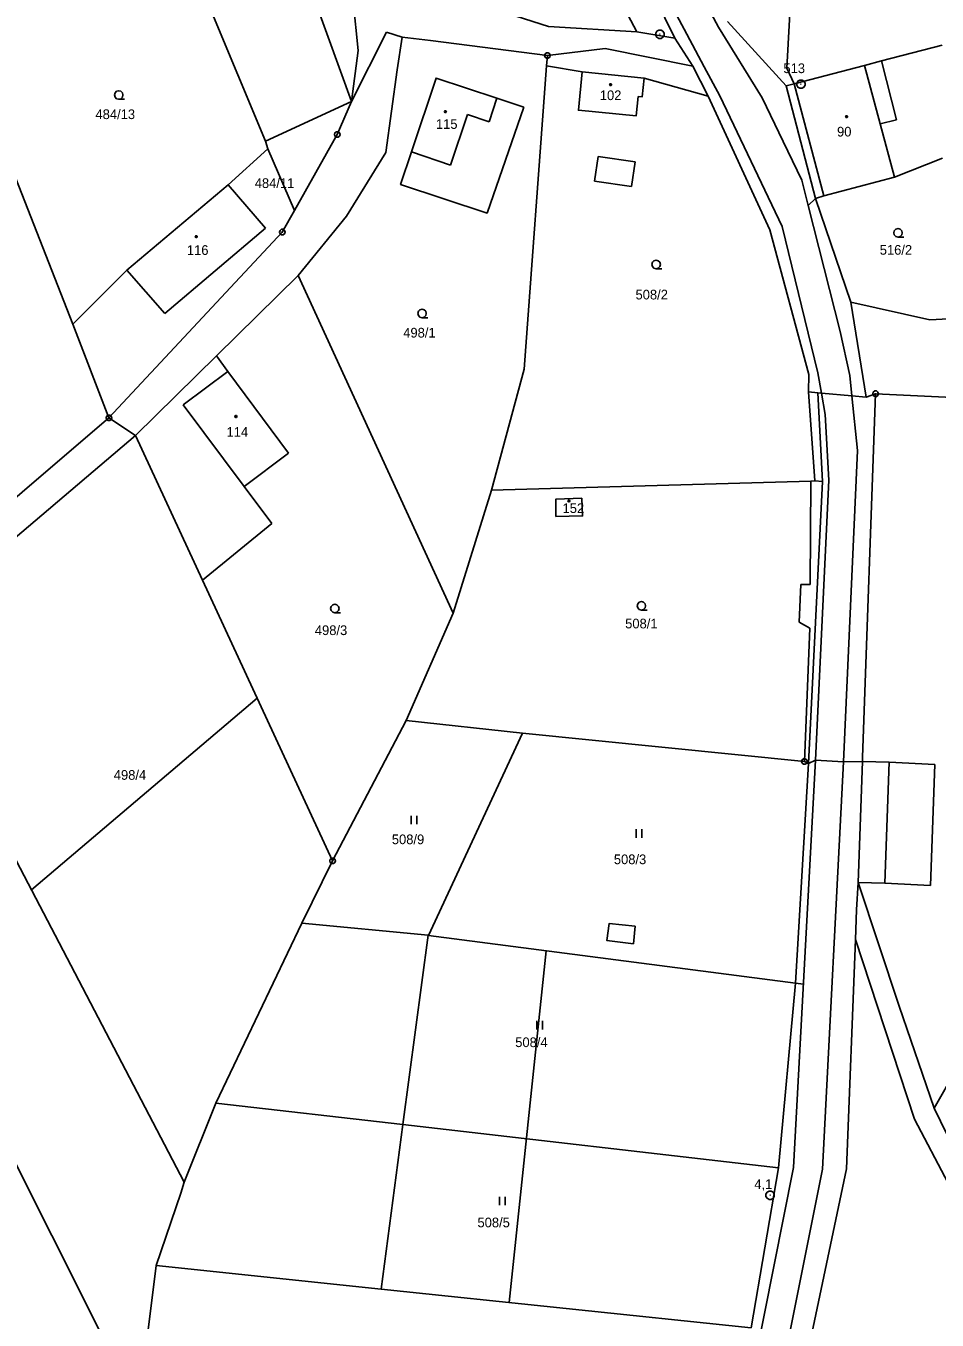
# Model space of a CAD drawing. Extents: x -694465 to -690527, y -983694 to -978978.
# Drawn here: x -693633.5 to -693473.5, y -981788.7 to -981561.4 of the extents above; entities that cross this region are included whole.
import ezdxf

# ---------------------------------------------------------------- set-up
doc = ezdxf.new("R2010")
doc.units = 0
for name, color, linetype in [('Vrstva 1', 7, 'Continuous'), ('Vrstva 17', 7, 'Continuous'), ('Vrstva 18', 7, 'Continuous'), ('Vrstva 19', 7, 'Continuous'), ('Vrstva 24', 7, 'Continuous'), ('Vrstva 25', 7, 'Continuous'), ('Vrstva 60', 7, 'Continuous')]:
    doc.layers.add(name, color=color, linetype=linetype)

msp = doc.modelspace()

# ---------------------------------------------------------------- linework, layer by layer
at = {"layer": 'Vrstva 1'}
for p, q in [((-693486.63, -981690.59), (-693481.922, -981690.723)), ((-693481.922, -981690.723), (-693482.682, -981711.945)), ((-693481.922, -981690.723), (-693473.892, -981691.119)), ((-693473.892, -981691.119), (-693474.652, -981712.341)), ((-693487.39, -981711.812), (-693482.682, -981711.945)), ((-693482.682, -981711.945), (-693474.652, -981712.341)), ((-693498.36, -981729.51), (-693496.987, -981729.689))]:
    msp.add_line(p, q, dxfattribs=at)
for points in [[(-693499.89, -981568.87), (-693496.96, -981515.34)], [(-693576.3, -981574.69), (-693591.231, -981533.472)], [(-693540.98, -981534.55), (-693526.2, -981562.45)], [(-693525.69, -981535.81), (-693511.89, -981561.65)], [(-693531.74, -981538.76), (-693519.54, -981563.57)], [(-693517.435, -981562.878), (-693530.46, -981538.43)], [(-693605.69, -981547.38), (-693591.42, -981581.65)], [(-693541.73, -981561.5), (-693563.32, -981554.55)], [(-693576.01, -981557.09), (-693575.12, -981565.72)], [(-693646.88, -981558.61), (-693625.23, -981613.78)], [(-693526.2, -981562.45), (-693541.73, -981561.5)], [(-693511.89, -981561.65), (-693504.23, -981574.04)], [(-693510.3, -981560.67), (-693500.03, -981571.95)], [(-693576.3, -981574.69), (-693570.16, -981562.54)], [(-693570.16, -981562.54), (-693567.39, -981563.42)], [(-693568.28, -981569.16), (-693567.39, -981563.42)], [(-693567.39, -981563.42), (-693562.43, -981564.01)], [(-693562.43, -981564.01), (-693541.91, -981566.62)], [(-693519.54, -981563.57), (-693526.2, -981562.45)], [(-693516.4, -981568.5), (-693519.54, -981563.57)], [(-693514.37, -981568.63), (-693517.435, -981562.878)], [(-693575.12, -981565.72), (-693576.3, -981574.69)], [(-693541.91, -981566.62), (-693531.79, -981565.36)], [(-693531.79, -981565.36), (-693516.4, -981568.5)], [(-693472.62, -981564.78), (-693483.26, -981567.56)], [(-693542.05, -981568.45), (-693546.02, -981621.69)], [(-693541.91, -981566.62), (-693542.05, -981568.45)], [(-693542.05, -981568.45), (-693535.79, -981569.48)], [(-693516.4, -981568.5), (-693513.67, -981573.74)], [(-693511.67, -981573.72), (-693514.37, -981568.63)], [(-693486.26, -981568.35), (-693498.58, -981571.57)], [(-693483.26, -981567.56), (-693486.26, -981568.35)], [(-693486.26, -981568.35), (-693483.49, -981578.6)], [(-693483.26, -981567.56), (-693480.65, -981577.9)], [(-693570.28, -981583.65), (-693568.28, -981569.16)], [(-693565.78, -981583.56), (-693561.47, -981570.58), (-693550.78, -981574.13)], [(-693526, -981573.79), (-693526.35, -981577.24), (-693536.47, -981576.22), (-693535.79, -981569.48)], [(-693535.79, -981569.48), (-693524.95, -981570.58)], [(-693524.95, -981570.58), (-693525.28, -981573.86), (-693526, -981573.79)], [(-693524.95, -981570.58), (-693513.67, -981573.74)], [(-693498.58, -981571.57), (-693499.89, -981568.87)], [(-693500.03, -981571.95), (-693498.58, -981571.57)], [(-693494.83, -981591.72), (-693500.03, -981571.95)], [(-693493.4, -981591.27), (-693498.58, -981571.57)], [(-693576.3, -981574.69), (-693591.42, -981581.65)], [(-693578.8, -981580.47), (-693576.3, -981574.69)], [(-693550.78, -981574.13), (-693552.15, -981578.26)], [(-693550.78, -981574.13), (-693546.03, -981575.7)], [(-693513.67, -981573.74), (-693502.85, -981597.21)], [(-693500.7, -981596.63), (-693511.67, -981573.72)], [(-693504.23, -981574.04), (-693500.538, -981581.716)], [(-693546.03, -981575.7), (-693552.5, -981594.3), (-693567.68, -981589.25), (-693565.78, -981583.56)], [(-693555.96, -981577), (-693558.9, -981585.85)], [(-693552.15, -981578.26), (-693555.96, -981577)], [(-693480.65, -981577.9), (-693483.49, -981578.6)], [(-693483.49, -981578.6), (-693481, -981587.97)], [(-693591.42, -981581.65), (-693591.01, -981583.01)], [(-693586.338, -981593.859), (-693578.8, -981580.47)], [(-693500.538, -981581.716), (-693497.27, -981588.51)], [(-693591.01, -981583.01), (-693597.98, -981589.32)], [(-693591.01, -981583.01), (-693586.338, -981593.859)], [(-693577.2, -981594.85), (-693570.28, -981583.65)], [(-693558.9, -981585.85), (-693565.78, -981583.56)], [(-693533.012, -981584.346), (-693533.632, -981588.684)], [(-693526.529, -981585.273), (-693533.012, -981584.346)], [(-693527.149, -981589.611), (-693526.529, -981585.273)], [(-693481, -981587.97), (-693472.55, -981584.65)], [(-693533.632, -981588.684), (-693527.149, -981589.611)], [(-693497.27, -981588.51), (-693496.133, -981592.971)], [(-693493.4, -981591.27), (-693481, -981587.97)], [(-693597.98, -981589.32), (-693615.73, -981604.32)], [(-693597.98, -981589.32), (-693591.41, -981596.93)], [(-693494.83, -981591.72), (-693493.4, -981591.27)], [(-693494.83, -981591.72), (-693496.133, -981592.971)], [(-693496.133, -981592.971), (-693490.5, -981615.07)], [(-693488.64, -981609.93), (-693494.83, -981591.72)], [(-693588.45, -981597.61), (-693586.338, -981593.859)], [(-693585.64, -981605.26), (-693577.2, -981594.85)], [(-693618.89, -981630.26), (-693588.45, -981597.61)], [(-693591.41, -981596.93), (-693609.1, -981611.92)], [(-693502.85, -981597.21), (-693496.02, -981622.65)], [(-693494.42, -981622.31), (-693500.7, -981596.63)], [(-693615.73, -981604.32), (-693625.23, -981613.78)], [(-693609.1, -981611.92), (-693615.73, -981604.32)], [(-693600.01, -981619.38), (-693585.64, -981605.26)], [(-693558.43, -981664.53), (-693585.64, -981605.26)], [(-693474.76, -981613.05), (-693488.64, -981609.93)], [(-693488.64, -981609.93), (-693485.97, -981626.61)], [(-693625.23, -981613.78), (-693618.89, -981630.26)], [(-693463.89, -981612.45), (-693474.76, -981613.05)], [(-693490.5, -981615.07), (-693488.81, -981622.8)], [(-693614.21, -981633.33), (-693600.01, -981619.38)], [(-693598.04, -981622.12), (-693600.01, -981619.38)], [(-693605.86, -981627.95), (-693598.04, -981622.12)], [(-693587.35, -981636.47), (-693598.04, -981622.12)], [(-693546.02, -981621.69), (-693551.71, -981642.94)], [(-693496.02, -981622.65), (-693496.06, -981625.68)], [(-693493.8, -981625.89), (-693494.42, -981622.31)], [(-693488.81, -981622.8), (-693488.45, -981626.38)], [(-693496.06, -981625.68), (-693494.46, -981625.83)], [(-693496.06, -981625.68), (-693494.99, -981641.32)], [(-693494.46, -981625.83), (-693493.65, -981641.41)], [(-693493.8, -981625.89), (-693494.46, -981625.83)], [(-693488.45, -981626.38), (-693493.8, -981625.89)], [(-693493.14, -981629.65), (-693493.8, -981625.89)], [(-693485.97, -981626.61), (-693488.45, -981626.38)], [(-693488.45, -981626.38), (-693487.47, -981635.98)], [(-693484.3, -981626), (-693486.62, -981689.84), (-693486.63, -981690.59)], [(-693485.97, -981626.61), (-693484.3, -981626)], [(-693460.987, -981627.12), (-693484.3, -981626)], [(-693595.17, -981642.3), (-693605.86, -981627.95)], [(-693492.5, -981641.2), (-693493.14, -981629.65)], [(-693618.89, -981630.26), (-693649.412, -981656.344)], [(-693618.89, -981630.26), (-693614.21, -981633.33)], [(-693655.78, -981668.61), (-693614.21, -981633.33)], [(-693614.21, -981633.33), (-693602.45, -981658.74)], [(-693595.17, -981642.3), (-693587.35, -981636.47)], [(-693487.47, -981635.98), (-693489.91, -981690.63)], [(-693495.65, -981641.34), (-693551.71, -981642.94)], [(-693495.65, -981641.34), (-693495.77, -981659.51)], [(-693494.99, -981641.32), (-693495.65, -981641.34)], [(-693493.65, -981641.41), (-693494.99, -981641.32)], [(-693494.87, -981690.36), (-693492.5, -981641.2)], [(-693590.28, -981648.79), (-693595.17, -981642.3)], [(-693551.71, -981642.94), (-693558.43, -981664.53)], [(-693493.65, -981641.41), (-693496.06, -981690.94)], [(-693535.85, -981644.36), (-693535.73, -981647.45), (-693540.43, -981647.54), (-693540.45, -981644.54), (-693535.85, -981644.36)], [(-693442.789, -981648.122), (-693447.364, -981687.022), (-693443.17, -981689.692), (-693454.607, -981723.253), (-693458.8, -981724.779), (-693474.048, -981751.475), (-693480.147, -981733.55), (-693487.39, -981711.812)], [(-693602.45, -981658.74), (-693590.28, -981648.79)], [(-693602.45, -981658.74), (-693579.63, -981708.03)], [(-693497.45, -981659.53), (-693497.7, -981666.09)], [(-693495.77, -981659.51), (-693497.45, -981659.53)], [(-693558.43, -981664.53), (-693566.7, -981683.41)], [(-693497.7, -981666.09), (-693495.85, -981667.19)], [(-693605.65, -981764.46), (-693655.78, -981668.61)], [(-693495.85, -981667.19), (-693496.8, -981690.58)], [(-693617.65, -981796.24), (-693673.94, -981684.03)], [(-693566.7, -981683.41), (-693579.63, -981708.03)], [(-693546.28, -981685.58), (-693566.7, -981683.41)], [(-693546.28, -981685.58), (-693562.77, -981721.11)], [(-693496.8, -981690.58), (-693546.28, -981685.58)], [(-693502.88, -981853.26), (-693502.9, -981847.67), (-693496.66, -981796.58), (-693489.44, -981762.11), (-693487.855, -981721.84), (-693487.65, -981716.64), (-693487.39, -981711.812), (-693486.63, -981690.59)], [(-693498.72, -981761.9), (-693494.87, -981690.36)], [(-693496.06, -981690.94), (-693498.36, -981729.51)], [(-693496.06, -981690.94), (-693496.8, -981690.58)], [(-693496.06, -981690.94), (-693494.87, -981690.36)], [(-693489.91, -981690.63), (-693494.87, -981690.36)], [(-693489.91, -981690.63), (-693493.6, -981762.16)], [(-693486.63, -981690.59), (-693489.91, -981690.63)], [(-693579.63, -981708.03), (-693585.03, -981718.97)], [(-693585.03, -981718.97), (-693600.12, -981750.56)], [(-693562.86, -981721.101), (-693585.03, -981718.97)], [(-693526.498, -981719.506), (-693526.809, -981722.583), (-693531.476, -981722.018), (-693531.078, -981719.044), (-693526.498, -981719.506)], [(-693562.86, -981721.101), (-693567.277, -981754.341)], [(-693562.77, -981721.11), (-693562.86, -981721.101)], [(-693498.36, -981729.51), (-693562.77, -981721.11)], [(-693434.784, -981803.343), (-693456.513, -981786.181), (-693465.661, -981775.883), (-693477.479, -981753.382), (-693487.855, -981721.84)], [(-693498.36, -981729.51), (-693501.36, -981761.93)], [(-693600.12, -981750.56), (-693605.65, -981764.46)], [(-693567.277, -981754.341), (-693600.12, -981750.56)], [(-693455.369, -981783.511), (-693463.755, -981772.451), (-693474.048, -981751.475)], [(-693567.277, -981754.341), (-693571.115, -981783.222)], [(-693501.36, -981761.93), (-693567.277, -981754.341)], [(-693501.36, -981761.93), (-693506.17, -981790.05)], [(-693505.54, -981796.36), (-693498.72, -981761.9)], [(-693493.6, -981762.16), (-693500.65, -981797.27)], [(-693606.29, -981766.35), (-693610.61, -981779.07)], [(-693605.65, -981764.46), (-693606.29, -981766.35)], [(-693610.61, -981779.07), (-693612.75, -981796.48)], [(-693610.61, -981779.07), (-693571.115, -981783.222)], [(-693571.115, -981783.222), (-693506.17, -981790.05)]]:
    msp.add_lwpolyline(points, dxfattribs=at)
at = {"layer": 'Vrstva 24'}
for points in [[(-693521.966, -981562.166), (-693521.63, -981562.36), (-693521.436, -981562.696), (-693521.436, -981563.084), (-693521.63, -981563.42), (-693521.966, -981563.614), (-693522.354, -981563.614), (-693522.69, -981563.42), (-693522.884, -981563.084), (-693522.884, -981562.696), (-693522.69, -981562.36), (-693522.354, -981562.166)], [(-693541.756, -981566.144), (-693541.506, -981566.326), (-693541.41, -981566.62), (-693541.506, -981566.914), (-693541.756, -981567.096), (-693542.064, -981567.096), (-693542.314, -981566.914), (-693542.41, -981566.62), (-693542.314, -981566.326), (-693542.064, -981566.144)], [(-693497.216, -981570.926), (-693496.88, -981571.12), (-693496.686, -981571.456), (-693496.686, -981571.844), (-693496.88, -981572.18), (-693497.216, -981572.374), (-693497.604, -981572.374), (-693497.94, -981572.18), (-693498.134, -981571.844), (-693498.134, -981571.456), (-693497.94, -981571.12), (-693497.604, -981570.926)], [(-693578.646, -981579.994), (-693578.396, -981580.176), (-693578.3, -981580.47), (-693578.396, -981580.764), (-693578.646, -981580.946), (-693578.954, -981580.946), (-693579.204, -981580.764), (-693579.3, -981580.47), (-693579.204, -981580.176), (-693578.954, -981579.994)], [(-693588.296, -981597.134), (-693588.046, -981597.316), (-693587.95, -981597.61), (-693588.046, -981597.904), (-693588.296, -981598.086), (-693588.604, -981598.086), (-693588.854, -981597.904), (-693588.95, -981597.61), (-693588.854, -981597.316), (-693588.604, -981597.134)], [(-693484.146, -981625.524), (-693483.896, -981625.706), (-693483.8, -981626), (-693483.896, -981626.294), (-693484.146, -981626.476), (-693484.454, -981626.476), (-693484.704, -981626.294), (-693484.8, -981626), (-693484.704, -981625.706), (-693484.454, -981625.524)], [(-693484.146, -981625.524), (-693483.896, -981625.706), (-693483.8, -981626), (-693483.896, -981626.294), (-693484.146, -981626.476), (-693484.454, -981626.476), (-693484.704, -981626.294), (-693484.8, -981626), (-693484.704, -981625.706), (-693484.454, -981625.524)], [(-693618.736, -981629.784), (-693618.486, -981629.966), (-693618.39, -981630.26), (-693618.486, -981630.554), (-693618.736, -981630.736), (-693619.044, -981630.736), (-693619.294, -981630.554), (-693619.39, -981630.26), (-693619.294, -981629.966), (-693619.044, -981629.784)], [(-693496.646, -981690.104), (-693496.396, -981690.286), (-693496.3, -981690.58), (-693496.396, -981690.874), (-693496.646, -981691.056), (-693496.954, -981691.056), (-693497.204, -981690.874), (-693497.3, -981690.58), (-693497.204, -981690.286), (-693496.954, -981690.104)], [(-693579.476, -981707.554), (-693579.226, -981707.736), (-693579.13, -981708.03), (-693579.226, -981708.324), (-693579.476, -981708.506), (-693579.784, -981708.506), (-693580.034, -981708.324), (-693580.13, -981708.03), (-693580.034, -981707.736), (-693579.784, -981707.554)], [(-693502.626, -981766.016), (-693502.29, -981766.21), (-693502.096, -981766.546), (-693502.096, -981766.934), (-693502.29, -981767.27), (-693502.626, -981767.464), (-693503.014, -981767.464), (-693503.35, -981767.27), (-693503.544, -981766.934), (-693503.544, -981766.546), (-693503.35, -981766.21), (-693503.014, -981766.016)]]:
    msp.add_lwpolyline(points, close=True, dxfattribs=at)
for points in [[(-693522.21, -981562.89), (-693522.11, -981562.89)], [(-693542.029, -981566.62), (-693541.79, -981566.62)], [(-693497.46, -981571.65), (-693497.36, -981571.65)], [(-693578.919, -981580.47), (-693578.68, -981580.47)], [(-693588.569, -981597.61), (-693588.33, -981597.61)], [(-693484.419, -981626), (-693484.18, -981626)], [(-693484.419, -981626), (-693484.18, -981626)], [(-693619.009, -981630.26), (-693618.77, -981630.26)], [(-693496.919, -981690.58), (-693496.68, -981690.58)], [(-693579.749, -981708.03), (-693579.51, -981708.03)], [(-693502.87, -981766.74), (-693502.77, -981766.74)]]:
    msp.add_lwpolyline(points, dxfattribs=at)
at = {"layer": 'Vrstva 25'}
for points in [[(-693617.17, -981574.3), (-693617.545, -981574.199), (-693617.819, -981573.925), (-693617.92, -981573.55), (-693617.819, -981573.175), (-693617.545, -981572.901), (-693617.17, -981572.8), (-693616.795, -981572.901), (-693616.521, -981573.175), (-693616.42, -981573.55), (-693616.521, -981573.925), (-693616.795, -981574.199), (-693617.17, -981574.3), (-693616.17, -981574.301)], [(-693480.37, -981598.51), (-693480.745, -981598.409), (-693481.019, -981598.135), (-693481.12, -981597.76), (-693481.019, -981597.385), (-693480.745, -981597.111), (-693480.37, -981597.01), (-693479.995, -981597.111), (-693479.721, -981597.385), (-693479.62, -981597.76), (-693479.721, -981598.135), (-693479.995, -981598.409), (-693480.37, -981598.51), (-693479.37, -981598.511)], [(-693522.84, -981604.05), (-693523.215, -981603.949), (-693523.489, -981603.675), (-693523.59, -981603.3), (-693523.489, -981602.925), (-693523.215, -981602.651), (-693522.84, -981602.55), (-693522.465, -981602.651), (-693522.191, -981602.925), (-693522.09, -981603.3), (-693522.191, -981603.675), (-693522.465, -981603.949), (-693522.84, -981604.05), (-693521.84, -981604.051)], [(-693563.92, -981612.66), (-693564.295, -981612.559), (-693564.569, -981612.285), (-693564.67, -981611.91), (-693564.569, -981611.535), (-693564.295, -981611.261), (-693563.92, -981611.16), (-693563.545, -981611.261), (-693563.271, -981611.535), (-693563.17, -981611.91), (-693563.271, -981612.285), (-693563.545, -981612.559), (-693563.92, -981612.66), (-693562.92, -981612.661)], [(-693579.23, -981664.47), (-693579.605, -981664.369), (-693579.879, -981664.095), (-693579.98, -981663.72), (-693579.879, -981663.345), (-693579.605, -981663.071), (-693579.23, -981662.97), (-693578.855, -981663.071), (-693578.581, -981663.345), (-693578.48, -981663.72), (-693578.581, -981664.095), (-693578.855, -981664.369), (-693579.23, -981664.47), (-693578.23, -981664.471)], [(-693525.42, -981664), (-693525.795, -981663.899), (-693526.069, -981663.625), (-693526.17, -981663.25), (-693526.069, -981662.875), (-693525.795, -981662.601), (-693525.42, -981662.5), (-693525.045, -981662.601), (-693524.771, -981662.875), (-693524.67, -981663.25), (-693524.771, -981663.625), (-693525.045, -981663.899), (-693525.42, -981664), (-693524.42, -981664.001)], [(-693565.81, -981700.11), (-693565.81, -981701.61)], [(-693564.81, -981701.61), (-693564.81, -981700.11)], [(-693526.36, -981702.47), (-693526.36, -981703.97)], [(-693525.36, -981703.97), (-693525.36, -981702.47)], [(-693543.76, -981736.13), (-693543.76, -981737.63)], [(-693542.76, -981737.63), (-693542.76, -981736.13)], [(-693550.34, -981767), (-693550.34, -981768.5)], [(-693549.34, -981768.5), (-693549.34, -981767)]]:
    msp.add_lwpolyline(points, dxfattribs=at)
for points in [[(-693530.733, -981571.588), (-693530.645, -981571.74), (-693530.733, -981571.892), (-693530.907, -981571.892), (-693530.995, -981571.74), (-693530.907, -981571.588)], [(-693559.733, -981576.328), (-693559.645, -981576.48), (-693559.733, -981576.632), (-693559.907, -981576.632), (-693559.995, -981576.48), (-693559.907, -981576.328)], [(-693489.303, -981577.208), (-693489.215, -981577.36), (-693489.303, -981577.512), (-693489.477, -981577.512), (-693489.565, -981577.36), (-693489.477, -981577.208)], [(-693603.463, -981598.268), (-693603.375, -981598.42), (-693603.463, -981598.572), (-693603.637, -981598.572), (-693603.725, -981598.42), (-693603.637, -981598.268)], [(-693596.513, -981629.858), (-693596.425, -981630.01), (-693596.513, -981630.162), (-693596.687, -981630.162), (-693596.775, -981630.01), (-693596.687, -981629.858)], [(-693538.063, -981644.678), (-693537.975, -981644.83), (-693538.063, -981644.982), (-693538.237, -981644.982), (-693538.325, -981644.83), (-693538.237, -981644.678)]]:
    msp.add_lwpolyline(points, close=True, dxfattribs=at)
at = {"layer": 'Vrstva 60'}
for p, q in [((-693632.504, -981713.115), (-693592.855, -981679.466)), ((-693548.609, -981785.588), (-693542.114, -981723.804))]:
    msp.add_line(p, q, dxfattribs=at)

# ---------------------------------------------------------------- texts
at = {"layer": 'Vrstva 17'}
for s, p in [('513', (-693500.488, -981569.71)), ('4,1', (-693505.593, -981765.65))]:
    msp.add_text(s, height=1.7, dxfattribs=at).set_placement(p)
at = {"layer": 'Vrstva 18'}
for s, p in [('484/13', (-693621.248, -981577.78)), ('484/11', (-693593.293, -981589.88)), ('516/2', (-693483.576, -981601.6)), ('508/2', (-693526.447, -981609.45)), ('498/1', (-693567.222, -981616.14)), ('508/1', (-693528.266, -981667.21)), ('498/3', (-693582.737, -981668.38)), ('498/4', (-693618.033, -981693.79)), ('508/9', (-693569.224, -981705.1)), ('508/3', (-693530.251, -981708.61)), ('508/4', (-693547.564, -981740.73)), ('508/5', (-693554.19, -981772.37))]:
    msp.add_text(s, height=1.7, dxfattribs=at).set_placement(p)
at = {"layer": 'Vrstva 19'}
for s, p in [('102', (-693532.717, -981574.45)), ('115', (-693561.485, -981579.5)), ('90', (-693491.072, -981580.84)), ('116', (-693605.198, -981601.63)), ('114', (-693598.238, -981633.56)), ('152', (-693539.257, -981646.95))]:
    msp.add_text(s, height=1.7, dxfattribs=at).set_placement(p)

doc.saveas('drawing.dxf')
